Universal Robots PolyScope program: Greifer_20220113.urp

Program Greifer_20220113 (installation=default directory=/home/ur/ursim-current/programs createdIn=1.8.11657.0 lastSavedIn=3.14.3.1031232 robotSerialNumber=2018339999)
Calibrated DH parameters: a=[-0.000089, -0.234068, -0.192478, 0.000074, 0.000031, 0]; d=[0.151953, -23.000573, 205.927535, -182.814329, 0.08529, 0.082391]; alpha=[1.573307, -0.003051, -0.000504, 1.571732, -1.572651, 0]; deltaTheta=[-0.000016, 0.291167, -0.737874, 0.44664, 0.000017, -0.000036]
BeforeStart
  receive_data := [6,0,0,0,0,0,0]
  Move_To_Pos := p[0,0,0,0,0,0]
  SuppressedNode
    CallSubProgram
  Script: socket_open("10.0.2.1",33)
  task := [0,0]
  coop := 0
Robot Program (runOnlyOnce=false)
  SuppressedNode
    Wait Sleep waitTime=2
  Script: task=socket_read_ascii_float(1)
  If task[1]≟2
    Call Position_auslesen
    task := [0,0]
  ElseIf task[1]≟1
    Call move_robot
  Wait Sleep waitTime=0.01
SubProgram greifer (keepSynchronizedWithDisk=false)
  SuppressedNode
    Script: RG2(40,40,0.0, True , False , False )
Thread Thread_1 (runOnlyOnce=false)
  If Move_To_Pos≠p[0,0,0,0,0,0]
    Script: movel(Move_To_Pos,a=0.2,v=0.2,r=0)
SubProgram -> move_robot
SubProgram -> Position_auslesen
SubProgram Position_auslesen (keepSynchronizedWithDisk=false)
  Script: pose_1=get_actual_tcp_pose()
  Script: socket_send_string(pose_1)
SubProgram move_robot (keepSynchronizedWithDisk=false)
  Script: receive_data=socket_read_ascii_float(6)
  If receive_data[0]≠6
    Script: socket_send_string("0")
  Else 
    Script: socket_send_string("1")
    pointer := 0
    Loop While (checkContinuously=false) expression=pointer<receive_data[0]
      Script: Move_To_Pos[pointer]=receive_data[pointer+1]
      pointer := pointer+1
    task := [0,0]
